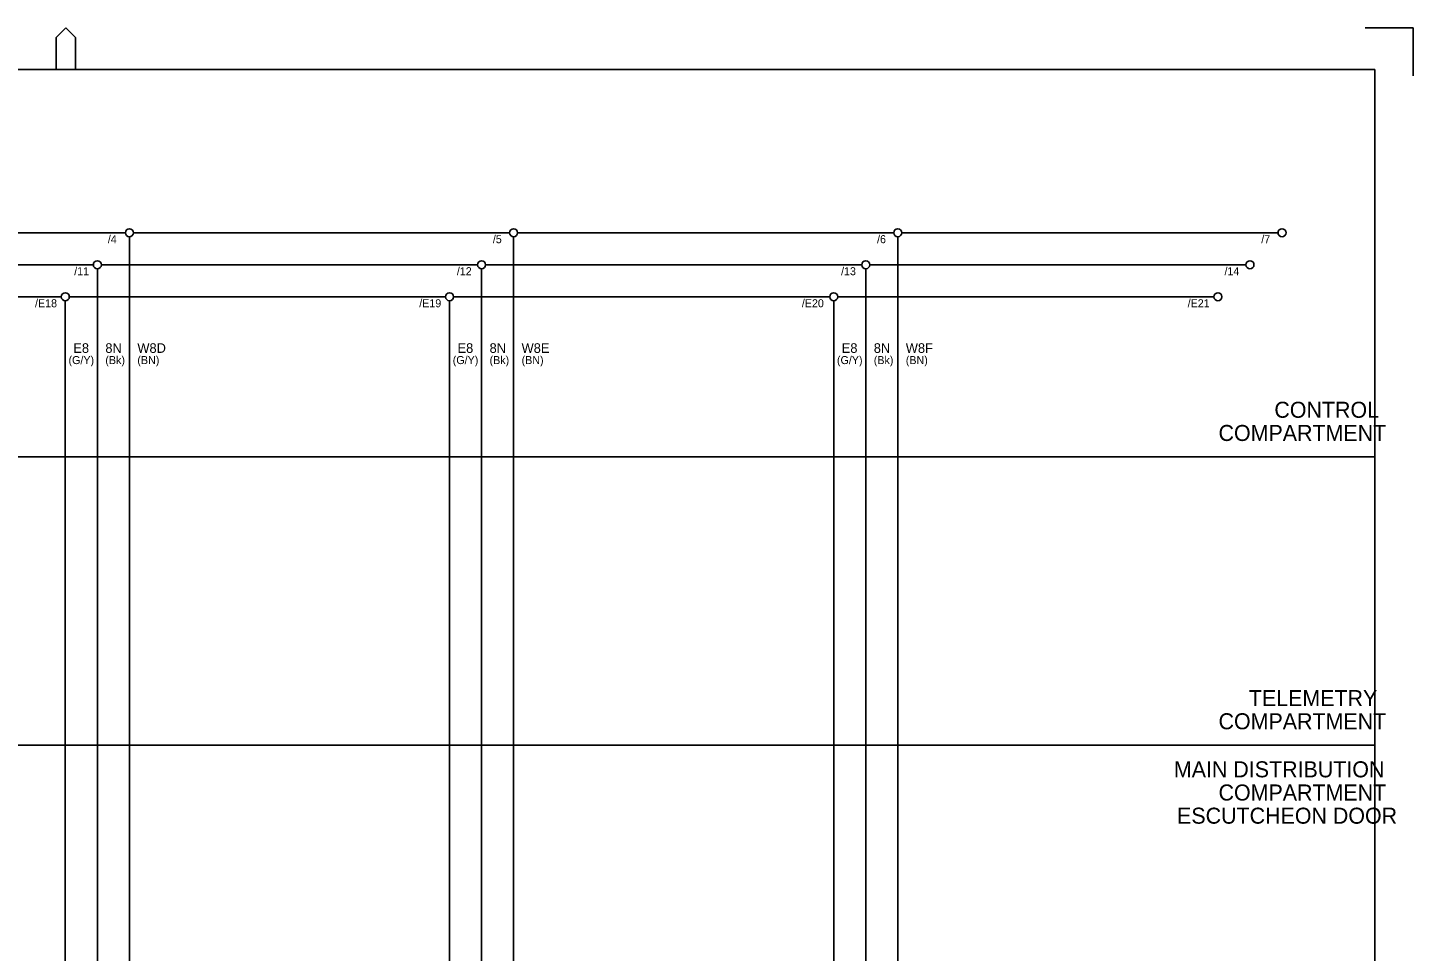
# Model space of a CAD drawing. Extents: x 0 to 841, y 0 to 594.
# Drawn here: x 408.3 to 841, y 305.7 to 594 of the extents above; entities that cross this region are included whole.
import ezdxf

# ---------------------------------------------------------------- set-up
doc = ezdxf.new("R2010")
doc.units = 0
doc.layers.add('A1BORDER', color=7, linetype='Continuous')
doc.layers.add('Level 1', color=7, linetype='Continuous')

msp = doc.modelspace()

# ---------------------------------------------------------------- linework, layer by layer
at = {"layer": 'A1BORDER'}
for p, q in [((417.19, 591), (420.19, 594)), ((423.19, 591), (420.19, 594)), ((826, 594), (841, 594)), ((841, 579), (841, 594)), ((417.19, 581), (417.19, 591)), ((423.19, 581), (423.19, 591)), ((28, 581), (829, 581)), ((829, 581), (829, 15))]:
    msp.add_line(p, q, dxfattribs=at)
at = {"layer": 'Level 1'}
for p, q in [((438.75, 530), (321.25, 530)), ((440, 255), (440, 528.75)), ((558.75, 530), (441.25, 530)), ((560, 255), (560, 528.75)), ((678.75, 530), (561.25, 530)), ((680, 255), (680, 528.75)), ((798.75, 530), (681.25, 530)), ((311.25, 520), (428.75, 520)), ((431.25, 520), (548.75, 520)), ((551.25, 520), (668.75, 520)), ((671.25, 520), (788.75, 520)), ((430, 107.5), (430, 518.75)), ((550, 107.5), (550, 518.75)), ((670, 107.5), (670, 518.75)), ((301.25, 510), (418.75, 510)), ((420, 118.75), (420, 508.75)), ((421.25, 510), (538.75, 510)), ((540, 118.75), (540, 508.75)), ((541.25, 510), (658.75, 510)), ((660, 118.75), (660, 508.75)), ((661.25, 510), (778.75, 510)), ((28, 460), (829, 460)), ((28, 370), (829, 370))]:
    msp.add_line(p, q, dxfattribs=at)
for centre in [(440, 530), (560, 530), (680, 530), (800, 530), (430, 520), (550, 520), (670, 520), (790, 520), (420, 510), (540, 510), (660, 510), (780, 510)]:
    msp.add_circle(centre, 1.25, dxfattribs=at)

# ---------------------------------------------------------------- texts
for s, height, p in [('/4', 2.50002, (433.26923, 526.73908)), ('/5', 2.50002, (553.51826, 526.73908)), ('/6', 2.50002, (673.51826, 526.73908)), ('/7', 2.50002, (793.51826, 526.73908)), ('/11', 2.50002, (422.77118, 516.73908)), ('/12', 2.50002, (542.27313, 516.73908)), ('/13', 2.50002, (662.27313, 516.73908)), ('/14', 2.50002, (782.02411, 516.73908)), ('/E18', 2.50002, (410.52995, 506.73908)), ('/E19', 2.50002, (530.52995, 506.73908)), ('/E20', 2.50002, (650.0319, 506.73908)), ('/E21', 2.50002, (770.52995, 506.73908)), ('E8', 3, (422.5, 492.49999)), ('8N', 3, (432.5, 492.49999)), ('W8D', 3, (442.5, 492.49999)), ('E8', 3, (542.5, 492.49999)), ('8N', 3, (552.5, 492.49999)), ('W8E', 3, (562.5, 492.49999)), ('E8', 3, (662.5, 492.49999)), ('8N', 3, (672.5, 492.49999)), ('W8F', 3, (682.5, 492.49999)), ('(G/Y)', 2.50002, (421, 488.99997)), ('(Bk)', 2.50002, (432.5, 488.99997)), ('(BN)', 2.50002, (442.5, 488.99997)), ('(G/Y)', 2.50002, (541, 488.99997)), ('(Bk)', 2.50002, (552.5, 488.99997)), ('(BN)', 2.50002, (562.5, 488.99997)), ('(G/Y)', 2.50002, (661, 488.99997)), ('(Bk)', 2.50002, (672.5, 488.99997)), ('(BN)', 2.50002, (682.5, 488.99997)), ('CONTROL', 5, (797.60547, 472.23633)), ('COMPARTMENT', 5, (780.17383, 465)), ('TELEMETRY', 5, (789.63672, 382.23633)), ('COMPARTMENT', 5, (780.17383, 375)), ('MAIN DISTRIBUTION', 5, (766.22852, 360)), ('COMPARTMENT', 5, (780.17383, 352.76367)), ('ESCUTCHEON DOOR', 5, (767.22461, 345.52734))]:
    msp.add_text(s, height=height, dxfattribs=at).set_placement(p)

doc.saveas('drawing.dxf')
